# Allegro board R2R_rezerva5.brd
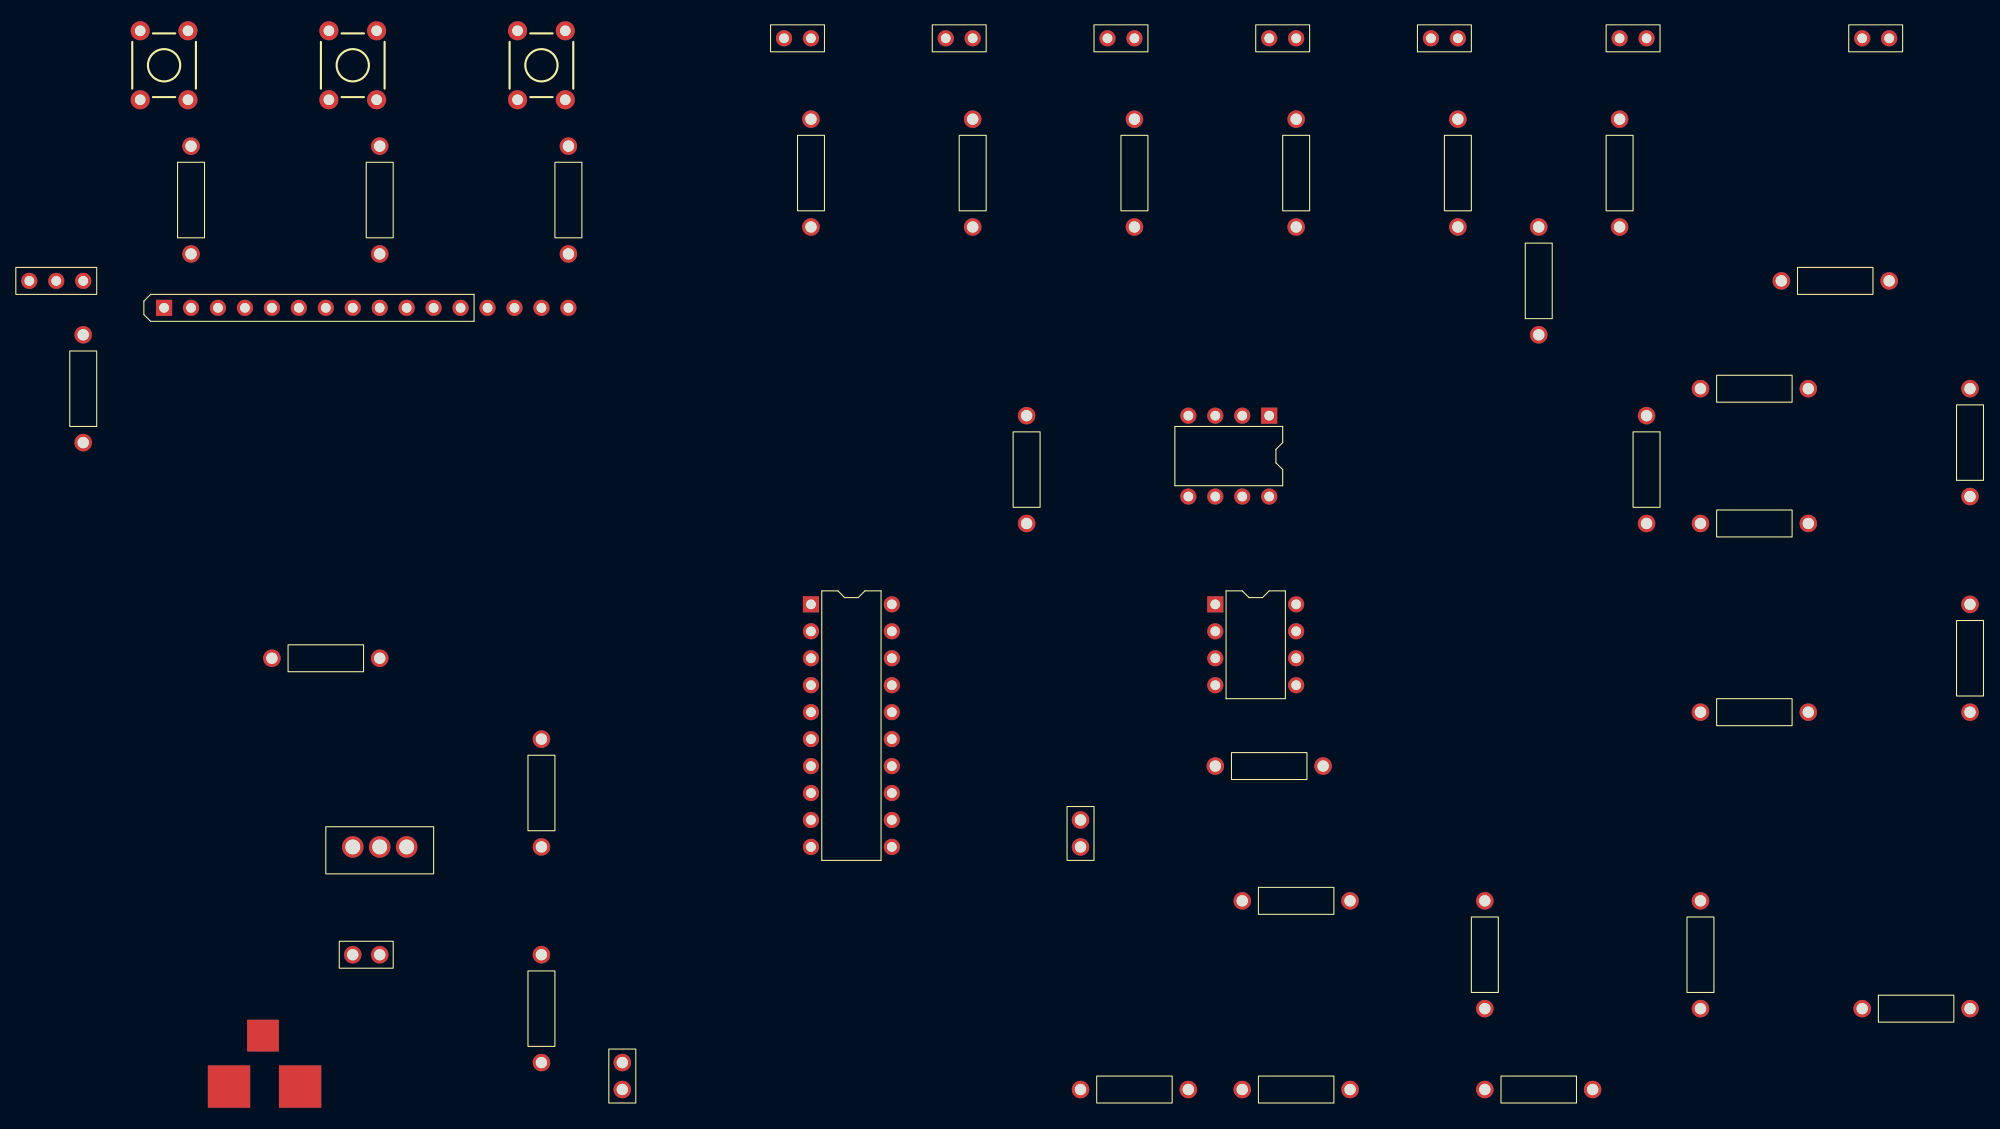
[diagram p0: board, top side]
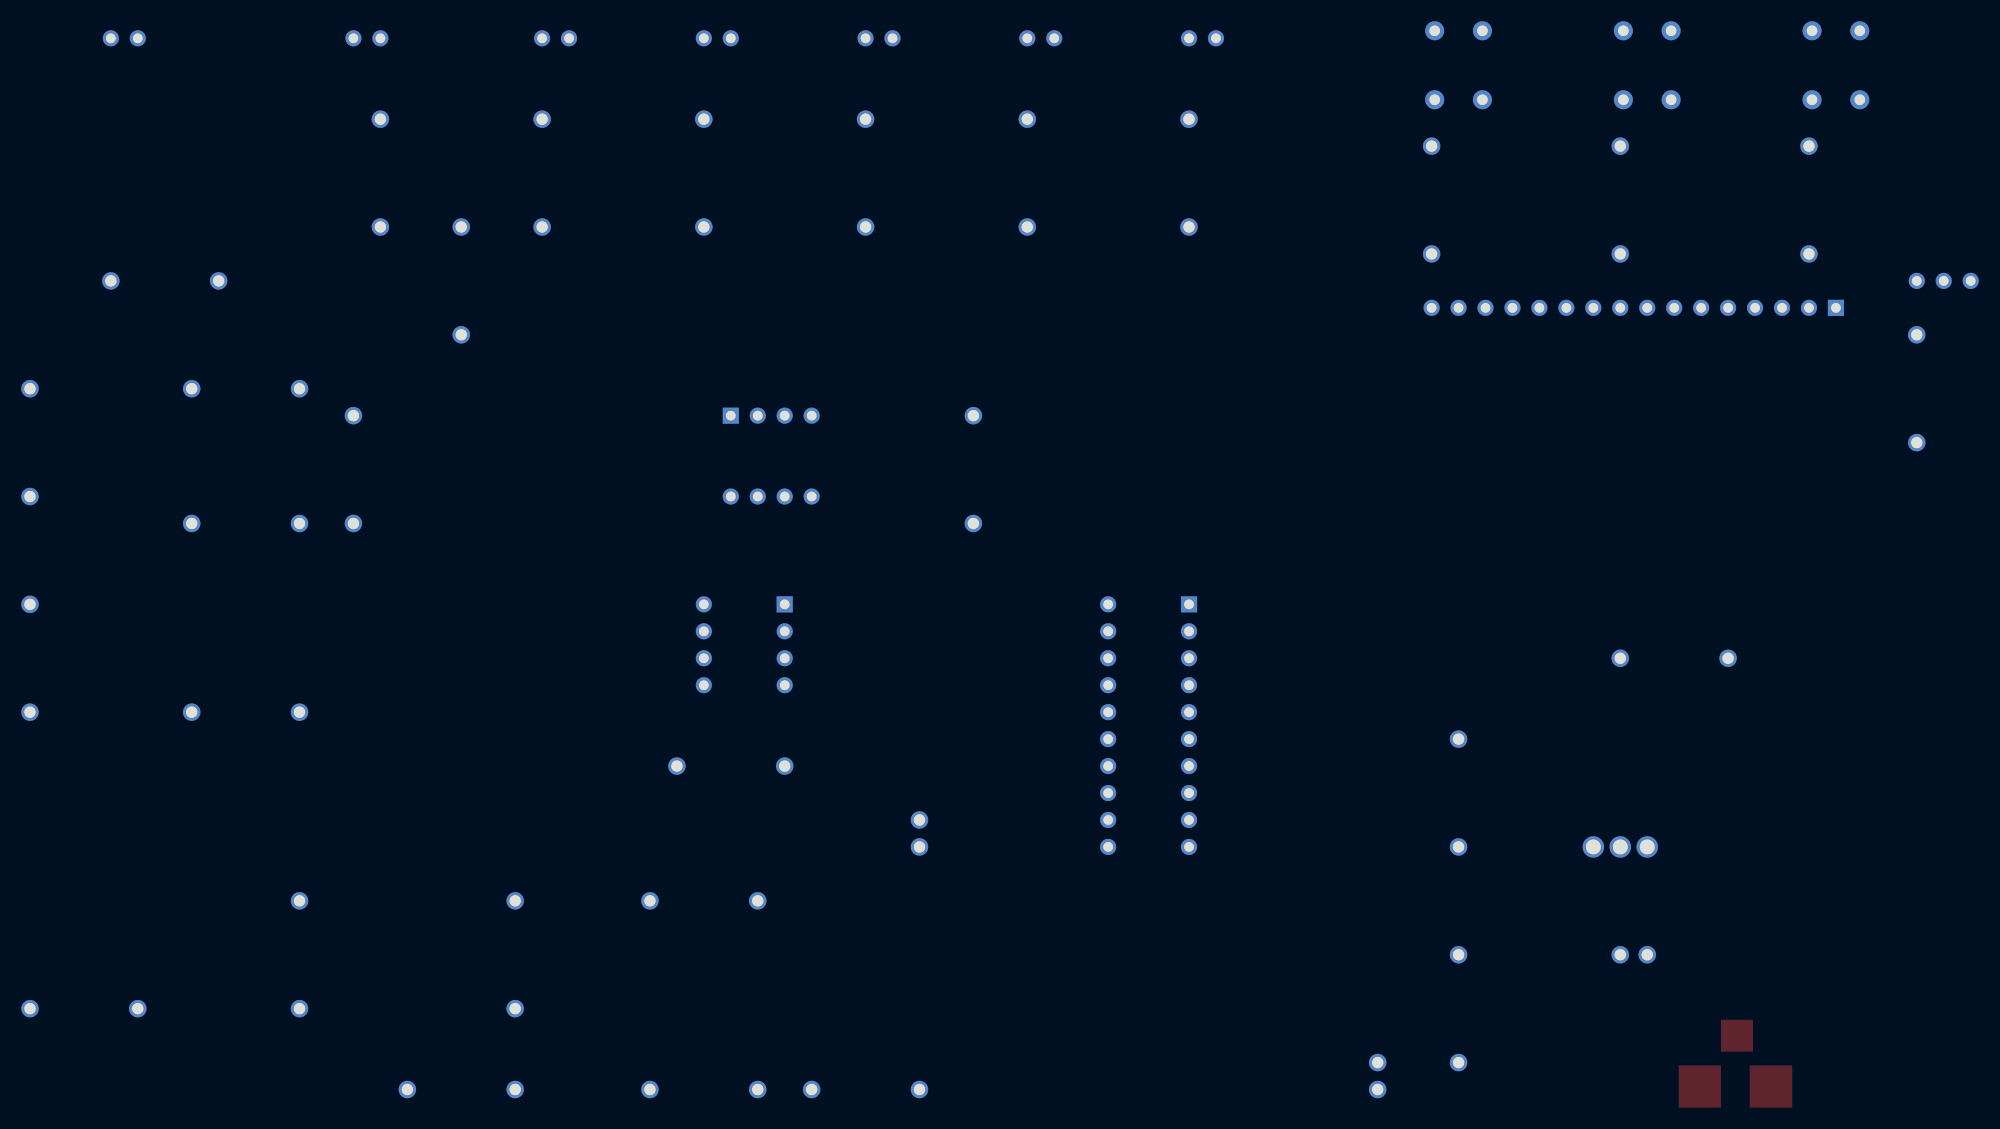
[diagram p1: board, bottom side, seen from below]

No outline. copper layers: TOP, BOTTOM. Coordinates in mm from the lowest, leftmost part position.

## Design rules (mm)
nets with their own width: min track width 0.7; nets N00328 N00332 N00336 N00340 N00355 N00470 N01662 N006340 N006500 N006660 N006820 N006980 N007140 N20855 N23488 N23661 N24189 N24193 N25824 N25853 N28143 N35057 N35516 N35592 N35638 N35656 N35674 N35692 N35721 N209781 SW1 SW2 SW3
nets with their own width: min track width 1; nets 0 9V V+ V- VCC

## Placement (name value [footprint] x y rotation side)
C3  10nf  [CAPCK05]  99.06 25.4 180 top
C4  10u  [CAPCK05]  30.48 12.7 270 top
C5  10u  [CAPCK05]  55.88 0 0 top
D1  MLED81  [JUMPER2]  71.12 99.06 0 top
D2  MLED81  [JUMPER2]  86.36 99.06 0 top
D3  MLED81  [JUMPER2]  101.6 99.06 0 top
D4  MLED81  [JUMPER2]  116.84 99.06 0 top
D5  MLED81  [JUMPER2]  132.08 99.06 0 top
D6  MLED81  [JUMPER2]  152.4 99.06 180 top
J1  Speaker  [JUMPER2]  172.72 99.06 0 top
J2  LCD 1602  [SIP16]  12.7 73.66 90 top
J3  CON3  [JACK_DC]  33.02 5.08 180 top
R2  1k  [RES400]  182.88 55.88 0 top
R3  1k  [RES400]  182.88 35.56 0 top
R4  1k  [RES400]  172.72 7.62 270 top
R5  1k  [RES400]  137.16 0 270 top
R6  1k  [RES400]  114.3 0 270 top
R7  2k  [RES400]  124.46 17.78 90 top
R8  2k  [RES400]  137.16 17.78 180 top
R9  2k  [RES400]  157.48 17.78 180 top
R10  2k  [RES400]  157.48 35.56 270 top
R11  2k  [RES400]  157.48 53.34 270 top
R12  2k  [RES400]  157.48 66.04 270 top
R13  2k  [RES400]  99.06 0 270 top
R14  470  [RES400]  149.86 81.28 0 top
R15  470  [RES400]  134.62 81.28 0 top
R16  470  [RES400]  119.38 81.28 0 top
R17  470  [RES400]  104.14 81.28 0 top
R18  470  [RES400]  88.9 81.28 0 top
R19  470  [RES400]  73.66 81.28 0 top
R20  10k  [RES400]  142.24 71.12 0 top
R22  10k  [RES400]  152.4 53.34 0 top
R23  1k  [RES400]  22.86 40.64 270 top
R24  470  [RES400]  48.26 22.86 0 top
R25  150  [RES400]  48.26 2.54 0 top
R26  33k  [RES400]  111.76 30.48 270 top
R27  10k  [RES400]  93.98 63.5 180 top
R28  10k  [RES400]  175.26 76.2 90 top
R29  1k  [JUMPER3]  0 76.2 0 top
R30  10k  [RES400]  15.24 88.9 180 top
R33  1k  [RES400]  5.08 60.96 0 top
R34  10k  [RES400]  33.02 88.9 180 top
R35  10k  [RES400]  50.8 88.9 180 top
SW7  SW_TC_SPST  [SW_SCHURTER_13019306L]  12.7 96.52 180 top
SW8  SW_TC_SPST  [SW_SCHURTER_13019306L]  30.48 96.52 180 top
SW9  SW_TC_SPST  [SW_SCHURTER_13019306L]  48.26 96.52 180 top
U1  MSP430G2553  [DIP20]  73.66 45.72 0 top
U7  LM317K  [TO220AB]  35.56 22.86 0 top
U9  LM358  [DIP8_3]  116.84 63.5 270 top
U10  LM358  [DIP8_3]  111.76 45.72 0 top

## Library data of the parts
C3-C5 = C: Tolerance: ***; User Part Number: ***
D1-D6 = MLED81: User Part Number: ***
J1 = CON2: User Part Number: ***
J2 = CON16: User Part Number: ***
J3 = CON3
R2-R20 R22-R28 R30 R33-R35 = R: Tolerance: ***; User Part Number: ***
R29 = POT: User Part Number: ***
SW7-SW9 = SW_TC_SPST
U1 = MSP430G2553_4: Tolerance: ***; User Part Number: ***
U7 = LM317T
U9 = LM358: Tolerance: ***; User Part Number: ***
U10 = LM358_0: Tolerance: ***; User Part Number: ***

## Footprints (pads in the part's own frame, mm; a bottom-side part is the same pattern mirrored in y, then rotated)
CAPCK05
  round 1.651 hole 1.067: 1(0,0) 2(0,2.54)
DIP8_3
  rect 1.524x1.524 hole 0.914: 1(0,0)
  round 1.524 hole 0.914: 2(0,-2.54) 3(0,-5.08) 4(0,-7.62) 5(7.62,-7.62) 6(7.62,-5.08) 7(7.62,-2.54) 8(7.62,0)
DIP20
  rect 1.524x1.524 hole 0.914: 1(0,0)
  round 1.524 hole 0.914: 2(0,-2.54) 3(0,-5.08) 4(0,-7.62) 5(0,-10.16) 6(0,-12.7) 7(0,-15.24) 8(0,-17.78) 9(0,-20.32) 10(0,-22.86) 11(7.62,-22.86) 12(7.62,-20.32) 13(7.62,-17.78) 14(7.62,-15.24) 15(7.62,-12.7) 16(7.62,-10.16) 17(7.62,-7.62) 18(7.62,-5.08) 19(7.62,-2.54) 20(7.62,0)
JACK_DC
  rect 4x4 smd: 1(7.5,4.8) 2(14.2,4.8)
  rect 3x3 smd: 3(11,0)
JUMPER2
  round 1.524 hole 0.914: 1(0,0) 2(2.54,0)
JUMPER3
  round 1.524 hole 0.914: 1(0,0) 2(2.54,0) 3(5.08,0)
RES400
  round 1.651 hole 1.067: 1(0,0) 2(0,10.16)
SIP16
  rect 1.524x1.524 hole 0.914: 1(0,0)
  round 1.524 hole 0.914: 2(0,-2.54) 3(0,-5.08) 4(0,-7.62) 5(0,-10.16) 6(0,-12.7) 7(0,-15.24) 8(0,-17.78) 9(0,-20.32) 10(0,-22.86) 11(0,-25.4) 12(0,-27.94) 13(0,-30.48) 14(0,-33.02) 15(0,-35.56) 16(0,-38.1)
SW_SCHURTER_13019306L
  round 1.8 hole 1: 1(-2.25,-3.25) 2(-2.25,3.25) 3(2.25,3.25) 4(2.25,-3.25)
TO220AB
  round 2.032 hole 1.397: 1(0,0) 2(-2.54,0) 3(-5.08,0)

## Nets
9V: C4.1 J3.1 U9.8(V+)
VCC: C5.2 J2.2 J2.16 R24.2 R30.2 R33.1 R34.2 R35.2 U1.1(DVCC) U7.3(OUT)
0: C3.2 C5.1 J2.1 J2.5 J3.2 J3.3 R13.1 R14.1 R15.1 R16.1 R17.1 R18.1 R19.1 R20.2 R23.1 R29.1 SW7.3 SW8.3 SW9.3 U1.20(GROUND) U9.4(V-) U9.5(+)
SW1: R30.1 SW7.1 SW7.2 U1.8(P2_0/CS(B0))
SW2: R34.1 SW8.1 SW8.2 U1.9(P2_1)
SW3: R35.1 SW9.1 SW9.2 U1.10(P2_2)
V+: U10.8(V+)
V-: U10.4(V-)
N00328: R2.1 R3.2 R11.2
N00332: R3.1 R4.2 R10.2
N00336: R4.1 R5.2 R9.2
N00340: R5.1 R6.2 R8.2
N00355: R2.2 R12.2 U10.3(+)
N00470: R6.1 R7.2 R13.2
N01662: D1.1(A) D2.1(A) D3.1(A) D4.1(A) D5.1(A) D6.1(A) R7.1 R8.1 R9.1 R10.1 R11.1 R12.1 U1.2(P1_0/A0/RED_LED) U1.3(P1_1/A1/RXD) U1.4(P1_2/A2/TXD) U1.5(P1_3/A3/PUSH2) U1.6(P1_4/A4) U1.7(P1_5/A5/SCK(B0))
N006340: D6.2(C) R14.2
N006500: D5.2(C) R15.2
N006660: D4.2(C) R16.2
N006820: D3.2(C) R17.2
N006980: D2.2(C) R18.2
N007140: D1.2(C) R19.2
N20855: R23.2 R25.1 U7.1(ADJ)
N23488: C3.1 R26.2 U9.3(+)
N23661: R26.1 U10.1(OUT) U10.2(-)
N24189: R20.1 R27.2 U9.2(-)
N24193: J1.1 R22.2 R27.1 U9.1(OUT)
N25824: R22.1 R28.2 U9.6(-)
N25853: J1.2 R28.1 U9.7(OUT)
N28143: C4.2 U7.2(IN)
N35057: J2.3 R29.2(T) R29.3(2)
N35516: J2.4 U1.11(P2_3)
N35592: J2.6 U1.12(P2_4)
N35638: J2.11 U1.13(P2_5)
N35656: J2.12 U1.14(P1_6/A6/SCL/MISO(B0)/GREEN LED)
N35674: J2.13 U1.15(P1_7/A7/SDA/MOSE(B0))
N35692: J2.14 U1.18(P2_7/XOUT)
N35721: J2.15 R33.2
N209781: R24.1 R25.2

Pads without a net: J2 7 8 9 10; SW7 4; SW8 4; SW9 4; U1 16 17 19; U10 5 6 7
